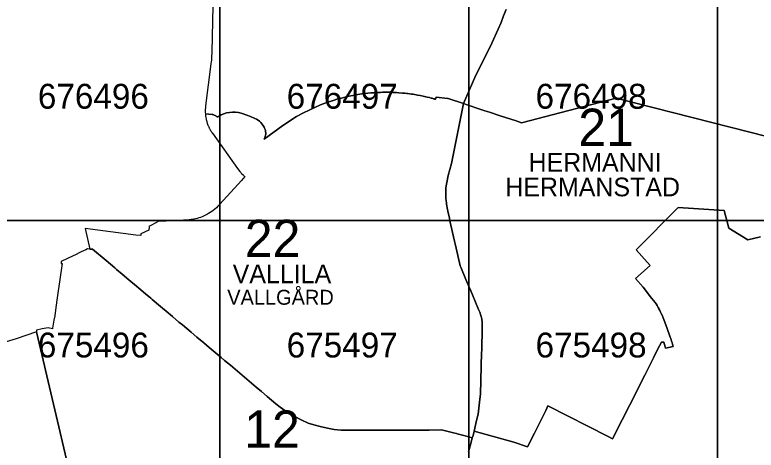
# Model space of a CAD drawing. Extents: x 25485000 to 25520000, y 6656775 to 6690000.
# Drawn here: x 25496176 to 25499155, y 6675077 to 6676827 of the extents above; entities that cross this region are included whole.
import ezdxf

# ---------------------------------------------------------------- set-up
doc = ezdxf.new("R2010")
doc.units = 0
doc.layers.add('Level 63', color=7, linetype='Continuous')

msp = doc.modelspace()

# ---------------------------------------------------------------- linework, layer by layer
at = {"layer": 'Level 63'}
for points in [[(25496000, 6676000), (25497000, 6676000), (25497000, 6677000), (25496000, 6677000)], [(25497000, 6676000), (25498000, 6676000), (25498000, 6677000), (25497000, 6677000)], [(25498000, 6676000), (25499000, 6676000), (25499000, 6677000), (25498000, 6677000)], [(25499000, 6676000), (25500000, 6676000), (25500000, 6677000), (25499000, 6677000)], [(25496458.3, 6675967.8), (25496477.4, 6675885.9), (25496487.8, 6675884.9), (25496542.4, 6675839.5), (25496577.6, 6675809.9), (25496585.2, 6675803.4), (25496606.7, 6675785.4), (25496634.6, 6675761.9), (25496664.8, 6675736.4), (25496674.1, 6675728.6), (25496700.5, 6675706.3), (25496722.3, 6675688), (25496728.4, 6675682.8), (25496736.1, 6675676.4), (25496752.9, 6675662.2), (25496769.7, 6675648.1), (25496783.5, 6675636.4), (25496809.4, 6675614.5), (25496835.4, 6675592.6), (25496849.2, 6675581), (25496866.8, 6675566.2), (25496884.4, 6675551.4), (25496907.4, 6675531.9), (25496934.9, 6675508.7), (25496956.3, 6675490.7), (25497005.3, 6675449.4), (25497019, 6675437.9), (25497042, 6675418.5), (25497145.9, 6675330.8), (25497167.3, 6675312.7), (25497189.6, 6675293.8), (25497207.4, 6675278.7), (25497225.2, 6675263.9), (25497242.3, 6675250.2), (25497271, 6675230), (25497298.1, 6675213.8), (25497326.1, 6675199.3), (25497355.1, 6675186.6), (25497377.1, 6675179), (25497403, 6675172), (25497431.8, 6675165.2), (25497459.8, 6675160.8), (25497487.8, 6675158.1), (25497516.4, 6675157.4), (25497540.6, 6675157.5), (25497558.6, 6675157.6), (25497586, 6675157.7), (25497620.4, 6675157.8), (25497659.4, 6675157.9), (25497700.1, 6675158), (25497725.6, 6675158.2), (25497751.6, 6675158.3), (25497771.6, 6675158.3), (25497840.1, 6675158.4), (25497841.1, 6675158.4), (25497891.1, 6675158.5), (25497938.7, 6675147.2), (25497950.8, 6675144.3), (25497952.9, 6675143.7), (25497985.6, 6675134.5), (25498014.4, 6675126.5), (25498017.2, 6675136.7), (25498021.4, 6675154.1), (25498031.6, 6675196.4), (25498037.8, 6675221.9), (25498045.2, 6675282.7), (25498047.6, 6675303.1), (25498051.9, 6675469.6), (25498052.1, 6675478.1), (25498052.5, 6675492.6), (25498054, 6675555.1), (25498054.6, 6675576.8), (25498054.2, 6675590.9), (25498052.3, 6675605), (25498049, 6675618.7), (25498044.3, 6675632), (25498044, 6675632.8), (25498039.5, 6675643.3), (25498027.5, 6675671.7), (25498015.1, 6675701.2), (25498004.2, 6675727.1), (25498001.8, 6675732.6), (25497988.8, 6675763.4), (25497967.8, 6675813.1), (25497965.7, 6675818.2), (25497956.4, 6675859.3), (25497945.6, 6675907.1), (25497943.4, 6675916.9), (25497924.6, 6675999.8), (25497922.4, 6676009.6), (25497917.1, 6676033), (25497917, 6676033.7), (25497916.5, 6676035.9), (25497916.1, 6676037.8), (25497915.6, 6676039.9), (25497915.4, 6676041.2), (25497914.9, 6676043.5), (25497914.6, 6676045.2), (25497914.2, 6676047), (25497913.9, 6676048.7), (25497913.6, 6676050.7), (25497913.1, 6676053), (25497912.8, 6676054.8), (25497912.6, 6676056.4), (25497911.9, 6676061), (25497911.3, 6676064.8), (25497910.6, 6676069.7), (25497910, 6676074.9), (25497909.7, 6676076.7), (25497909.4, 6676079.1), (25497909, 6676082.2), (25497908.4, 6676087.7), (25497908.3, 6676089.9), (25497908.1, 6676091.5), (25497908, 6676092.7), (25497907.9, 6676094.3), (25497907.9, 6676095.6), (25497907.7, 6676098.2), (25497907.6, 6676102.3), (25497907.5, 6676103.1), (25497907.5, 6676103.5), (25497907.5, 6676106.3), (25497907.5, 6676107.8), (25497907.5, 6676108.7), (25497907.5, 6676110.8), (25497907.5, 6676113.4), (25497907.6, 6676116.4), (25497907.6, 6676118), (25497907.7, 6676119.7), (25497907.8, 6676121.3), (25497908.1, 6676126.4), (25497908.2, 6676127.3), (25497908.2, 6676127.6), (25497908.3, 6676128.5), (25497908.4, 6676129.2), (25497908.5, 6676130.5), (25497909.6, 6676140.6), (25497911.6, 6676153.5), (25497917, 6676181.8), (25497930.1, 6676229.9), (25497978.7, 6676470.5), (25497917, 6676490.8), (25497916.1, 6676490.9), (25497869.1, 6676496.1), (25497866.1, 6676488.1), (25497863.3, 6676488.9), (25497863, 6676489), (25497862.7, 6676489.1), (25497859, 6676490.1), (25497855.4, 6676491.1), (25497852.7, 6676491.9), (25497851.3, 6676492.2), (25497849.5, 6676492.7), (25497841.7, 6676494.7), (25497833.2, 6676496.8), (25497816.8, 6676500.4), (25497805.2, 6676502.8), (25497793.5, 6676505), (25497776.1, 6676507.9), (25497770.4, 6676508.7), (25497763, 6676509.8), (25497755.4, 6676510.7), (25497751.7, 6676511.2), (25497742.8, 6676512.2), (25497737.8, 6676512.7), (25497734.1, 6676513), (25497719.6, 6676514.2), (25497710.2, 6676514.8), (25497694.9, 6676515.6), (25497684.4, 6676515.9), (25497673.4, 6676516), (25497662, 6676516), (25497653.4, 6676515.9), (25497645.1, 6676515.7), (25497631.9, 6676515.1), (25497619.8, 6676514.4), (25497606.8, 6676513.4), (25497594.6, 6676512.2), (25497582.3, 6676510.8), (25497570.8, 6676509.3), (25497555, 6676506.9), (25497543.3, 6676505), (25497534, 6676503.2), (25497526.2, 6676501.7), (25497512.5, 6676498.7), (25497497.6, 6676495.2), (25497488.8, 6676493), (25497480.7, 6676490.8), (25497469.6, 6676487.7), (25497459.8, 6676484.7), (25497446.6, 6676480.6), (25497443.2, 6676479.4), (25497442.4, 6676479.2), (25497436.8, 6676477.3), (25497431.5, 6676475.4), (25497426.3, 6676473.6), (25497414.8, 6676469.3), (25497404.5, 6676465.2), (25497336.4, 6676433.8), (25497310.9, 6676419.4), (25497308.1, 6676418), (25497253.5, 6676382.5), (25497178.5, 6676327.5), (25497181.6, 6676336.4), (25497182.2, 6676338.4), (25497183.4, 6676343.1), (25497184, 6676347.9), (25497184.2, 6676352.7), (25497183.8, 6676357.5), (25497182.9, 6676362.2), (25497181.6, 6676366.8), (25497179.8, 6676371.3), (25497177.5, 6676375.5), (25497172.7, 6676383.3), (25497169.2, 6676388.6), (25497164.5, 6676394.3), (25497159.3, 6676399.4), (25497153.6, 6676404), (25497147.4, 6676407.9), (25497140.8, 6676411.2), (25497122.5, 6676419.1), (25497092.9, 6676429.7), (25497085.7, 6676432), (25497074.2, 6676434.7), (25497062.5, 6676436.1), (25497050.6, 6676436.3), (25497038.8, 6676435.2), (25497027.2, 6676432.9), (25497015.9, 6676429.4), (25497005.1, 6676424.8), (25496994.7, 6676419), (25496994, 6676418.6), (25496993.3, 6676418.3), (25496992.5, 6676418), (25496991.6, 6676417.9), (25496990.8, 6676417.8), (25496990, 6676417.8), (25496989.1, 6676417.9), (25496988.3, 6676418.1), (25496987.5, 6676418.4), (25496986.8, 6676418.7), (25496986, 6676419.1), (25496985.4, 6676419.6), (25496983.1, 6676421.3), (25496980.4, 6676423), (25496977.6, 6676424.3), (25496974.6, 6676425.4), (25496971.6, 6676426.1), (25496968.4, 6676426.5), (25496941.6, 6676429.3), (25496941.7, 6676427.7), (25496941.7, 6676427.3), (25496941.8, 6676426.3), (25496941.9, 6676425.3), (25496942, 6676424.3), (25496942.2, 6676423), (25496942.5, 6676420.1), (25496942.9, 6676417.1), (25496943.4, 6676414.3), (25496944.4, 6676408.9), (25496944.9, 6676407), (25496945, 6676406.3), (25496945.9, 6676402.6), (25496946.9, 6676399), (25496947.7, 6676396), (25496948.6, 6676393.4), (25496949.2, 6676391.4), (25496950.7, 6676387.4), (25496951.9, 6676384.2), (25496952.9, 6676381.7), (25496954, 6676379.3), (25496955.5, 6676375.8), (25496956.5, 6676373.9), (25496957.5, 6676371.9), (25496958.5, 6676369.9), (25496959.8, 6676367.4), (25496959.9, 6676367.3), (25496960.8, 6676365.7), (25496961.4, 6676364.7), (25496961.7, 6676364.1), (25496961.9, 6676363.7), (25496962.4, 6676363), (25496962.6, 6676362.6), (25496963.7, 6676360.8), (25496964.8, 6676359), (25496965.9, 6676357.4), (25496966.5, 6676356.4), (25496967, 6676355.8), (25496968.1, 6676354.2), (25496968.6, 6676353.3), (25496968.8, 6676353.2), (25496969.1, 6676352.7), (25496969.3, 6676352.4), (25496969.4, 6676352.3), (25496970, 6676351.4), (25497071.4, 6676210.1), (25497080.5, 6676197.3), (25497083.6, 6676193.6), (25497085.7, 6676191.2), (25497088.3, 6676188.4), (25497092.9, 6676183.6), (25497095.6, 6676181.1), (25497097.9, 6676179), (25497100.3, 6676176.9), (25497086.7, 6676161.9), (25497044.1, 6676114.7), (25496999, 6676064.8), (25496992.4, 6676057.8), (25496986.1, 6676051.8), (25496980.3, 6676046.7), (25496973.6, 6676041.4), (25496967.9, 6676037.2), (25496960.7, 6676032.3), (25496954.9, 6676028.7), (25496950, 6676025.9), (25496944.7, 6676023), (25496938.9, 6676020.2), (25496933.5, 6676017.8), (25496928.2, 6676015.5), (25496922.3, 6676013.3), (25496914.9, 6676010.8), (25496909, 6676009), (25496902.4, 6676007.4), (25496895.6, 6676005.9), (25496891, 6676005), (25496884.7, 6676004.1), (25496876, 6676003), (25496784.4, 6675998.6), (25496754.5, 6675997.7), (25496725.5, 6675982.2), (25496715, 6675976.5), (25496715.7, 6675973.6), (25496714.6, 6675962.1), (25496682.4, 6675946.9), (25496681.7, 6675939.9), (25496662.9, 6675942.3)], [(25496000, 6675000), (25497000, 6675000), (25497000, 6676000), (25496000, 6676000)], [(25497000, 6675000), (25498000, 6675000), (25498000, 6676000), (25497000, 6676000)], [(25498000, 6675000), (25499000, 6675000), (25499000, 6676000), (25498000, 6676000)], [(25499000, 6675000), (25500000, 6675000), (25500000, 6676000), (25499000, 6676000)]]:
    msp.add_lwpolyline(points, close=True, dxfattribs=at)
for points in [[(25496973.3, 6676926.7), (25496967.4, 6676676.9), (25496967.3, 6676672.8), (25496966.9, 6676661.2), (25496966.5, 6676655.4), (25496966.1, 6676650.3), (25496965.7, 6676645.1), (25496964.9, 6676638), (25496964.1, 6676631), (25496942.8, 6676461.3), (25496942.5, 6676459.5), (25496942.3, 6676457.5), (25496942.2, 6676457.1), (25496942.2, 6676456.7), (25496942.1, 6676456.2), (25496942, 6676454.9), (25496941.9, 6676453.9), (25496941.8, 6676452.8), (25496941.8, 6676452.5), (25496941.7, 6676452.3), (25496941.6, 6676451.2), (25496941.6, 6676450.8), (25496941.4, 6676448.4), (25496941.4, 6676447), (25496941.3, 6676445.6), (25496941.3, 6676444.3), (25496941.2, 6676442.3), (25496941.2, 6676441), (25496941.2, 6676438.5), (25496941.2, 6676437.9), (25496941.2, 6676437.4), (25496941.2, 6676437), (25496941.2, 6676436.8), (25496941.3, 6676436.3), (25496941.3, 6676435.9), (25496941.3, 6676434.7), (25496941.6, 6676429.3), (25496941.7, 6676427.7), (25496941.7, 6676427.3), (25496941.8, 6676426.3), (25496941.9, 6676425.3), (25496942, 6676424.3), (25496942.2, 6676423), (25496942.5, 6676420.1), (25496942.9, 6676417.1), (25496943.4, 6676414.3), (25496944.4, 6676408.9), (25496944.9, 6676407), (25496945, 6676406.3), (25496945.9, 6676402.6), (25496946.9, 6676399), (25496947.7, 6676396), (25496948.6, 6676393.4), (25496949.2, 6676391.4), (25496950.7, 6676387.4), (25496951.9, 6676384.2), (25496952.9, 6676381.7), (25496954, 6676379.3), (25496955.5, 6676375.8), (25496956.5, 6676373.9), (25496957.5, 6676371.9), (25496958.5, 6676369.9), (25496959.8, 6676367.4), (25496959.9, 6676367.3), (25496960.8, 6676365.7), (25496961.4, 6676364.7), (25496961.7, 6676364.1), (25496961.9, 6676363.7), (25496962.4, 6676363), (25496962.6, 6676362.6), (25496963.7, 6676360.8), (25496964.8, 6676359), (25496965.9, 6676357.4), (25496966.5, 6676356.4), (25496967, 6676355.8), (25496968.1, 6676354.2), (25496968.6, 6676353.3), (25496968.8, 6676353.2), (25496969.1, 6676352.7), (25496969.3, 6676352.4), (25496969.4, 6676352.3), (25496970, 6676351.4), (25497071.4, 6676210.1), (25497080.5, 6676197.3), (25497083.6, 6676193.6), (25497085.7, 6676191.2), (25497088.3, 6676188.4), (25497092.9, 6676183.6), (25497095.6, 6676181.1), (25497097.9, 6676179), (25497100.3, 6676176.9), (25497086.7, 6676161.9), (25497044.1, 6676114.7), (25496999, 6676064.8), (25496992.4, 6676057.8), (25496986.1, 6676051.8), (25496980.3, 6676046.7), (25496973.6, 6676041.4), (25496967.9, 6676037.2), (25496960.7, 6676032.3), (25496954.9, 6676028.7), (25496950, 6676025.9), (25496944.7, 6676023), (25496938.9, 6676020.2), (25496933.5, 6676017.8), (25496928.2, 6676015.5), (25496922.3, 6676013.3), (25496914.9, 6676010.8), (25496909, 6676009), (25496902.4, 6676007.4), (25496895.6, 6676005.9), (25496891, 6676005), (25496884.7, 6676004.1), (25496876, 6676003), (25496784.4, 6675998.6), (25496754.5, 6675997.7), (25496725.5, 6675982.2), (25496715, 6675976.5), (25496715.7, 6675973.6), (25496714.6, 6675962.1), (25496682.4, 6675946.9), (25496681.7, 6675939.9), (25496662.9, 6675942.3), (25496458.3, 6675967.8), (25496477.4, 6675885.9), (25496467.6, 6675886.9), (25496460.7, 6675883), (25496442.6, 6675874.1), (25496437.2, 6675871.4), (25496419.5, 6675862.9), (25496410.7, 6675858.5), (25496362.7, 6675835.2), (25496361.9, 6675828), (25496366.4, 6675827.5), (25496345.8, 6675689.9), (25496341.2, 6675650.5), (25496337.4, 6675617.7), (25496332.4, 6675599.9), (25496327.6, 6675567.6), (25496327, 6675564.5), (25496310.6, 6675568.6), (25496286, 6675564.7), (25496262.6, 6675559.9), (25496263.6, 6675552.9), (25496181, 6675525.5), (25496141, 6675513.5)], [(25496973.3, 6676926.7), (25496967.4, 6676676.9), (25496967.3, 6676672.8), (25496966.9, 6676661.2), (25496966.5, 6676655.4), (25496966.1, 6676650.3), (25496965.7, 6676645.1), (25496964.9, 6676638), (25496964.1, 6676631), (25496942.8, 6676461.3), (25496942.5, 6676459.5), (25496942.3, 6676457.5), (25496942.2, 6676457.1), (25496942.2, 6676456.7), (25496942.1, 6676456.2), (25496942, 6676454.9), (25496941.9, 6676453.9), (25496941.8, 6676452.8), (25496941.8, 6676452.5), (25496941.7, 6676452.3), (25496941.6, 6676451.2), (25496941.6, 6676450.8), (25496941.4, 6676448.4), (25496941.4, 6676447), (25496941.3, 6676445.6), (25496941.3, 6676444.3), (25496941.2, 6676442.3), (25496941.2, 6676441), (25496941.2, 6676438.5), (25496941.2, 6676437.9), (25496941.2, 6676437.4), (25496941.2, 6676437), (25496941.2, 6676436.8), (25496941.3, 6676436.3), (25496941.3, 6676435.9), (25496941.3, 6676434.7), (25496941.6, 6676429.3), (25496968.4, 6676426.5), (25496971.6, 6676426.1), (25496974.6, 6676425.4), (25496977.6, 6676424.3), (25496980.4, 6676423), (25496983.1, 6676421.3), (25496985.4, 6676419.6), (25496986, 6676419.1), (25496986.8, 6676418.7), (25496987.5, 6676418.4), (25496988.3, 6676418.1), (25496989.1, 6676417.9), (25496990, 6676417.8), (25496990.8, 6676417.8), (25496991.6, 6676417.9), (25496992.5, 6676418), (25496993.3, 6676418.3), (25496994, 6676418.6), (25496994.7, 6676419), (25497005.1, 6676424.8), (25497015.9, 6676429.4), (25497027.2, 6676432.9), (25497038.8, 6676435.2), (25497050.6, 6676436.3), (25497062.5, 6676436.1), (25497074.2, 6676434.7), (25497085.7, 6676432), (25497092.9, 6676429.7), (25497122.5, 6676419.1), (25497140.8, 6676411.2), (25497147.4, 6676407.9), (25497153.6, 6676404), (25497159.3, 6676399.4), (25497164.5, 6676394.3), (25497169.2, 6676388.6), (25497172.7, 6676383.3), (25497177.5, 6676375.5), (25497179.8, 6676371.3), (25497181.6, 6676366.8), (25497182.9, 6676362.2), (25497183.8, 6676357.5), (25497184.2, 6676352.7), (25497184, 6676347.9), (25497183.4, 6676343.1), (25497182.2, 6676338.4), (25497181.6, 6676336.4), (25497178.5, 6676327.5), (25497253.5, 6676382.5), (25497308.1, 6676418), (25497310.9, 6676419.4), (25497336.4, 6676433.8), (25497404.5, 6676465.2), (25497414.8, 6676469.3), (25497426.3, 6676473.6), (25497431.5, 6676475.4), (25497436.8, 6676477.3), (25497442.4, 6676479.2), (25497443.2, 6676479.4), (25497446.6, 6676480.6), (25497459.8, 6676484.7), (25497469.6, 6676487.7), (25497480.7, 6676490.8), (25497488.8, 6676493), (25497497.6, 6676495.2), (25497512.5, 6676498.7), (25497526.2, 6676501.7), (25497534, 6676503.2), (25497543.3, 6676505), (25497555, 6676506.9), (25497570.8, 6676509.3), (25497582.3, 6676510.8), (25497594.6, 6676512.2), (25497606.8, 6676513.4), (25497619.8, 6676514.4), (25497631.9, 6676515.1), (25497645.1, 6676515.7), (25497653.4, 6676515.9), (25497662, 6676516), (25497673.4, 6676516), (25497684.4, 6676515.9), (25497694.9, 6676515.6), (25497710.2, 6676514.8), (25497719.6, 6676514.2), (25497734.1, 6676513), (25497737.8, 6676512.7), (25497742.8, 6676512.2), (25497751.7, 6676511.2), (25497755.4, 6676510.7), (25497763, 6676509.8), (25497770.4, 6676508.7), (25497776.1, 6676507.9), (25497793.5, 6676505), (25497805.2, 6676502.8), (25497816.8, 6676500.4), (25497833.2, 6676496.8), (25497841.7, 6676494.7), (25497849.5, 6676492.7), (25497851.3, 6676492.2), (25497852.7, 6676491.9), (25497855.4, 6676491.1), (25497859, 6676490.1), (25497862.7, 6676489.1), (25497863, 6676489), (25497863.3, 6676488.9), (25497866.1, 6676488.1), (25497869.1, 6676496.1), (25497916.1, 6676490.9), (25497917, 6676490.8), (25497978.7, 6676470.5), (25498001.4, 6676523.1), (25498027.9, 6676584.3), (25498049, 6676623.9), (25498092.4, 6676713.1), (25498118.2, 6676769.2), (25498129.7, 6676796.5), (25498140.1, 6676822.7), (25498149.9, 6676849)], [(25498149.9, 6676849), (25498140.1, 6676822.7), (25498129.7, 6676796.5), (25498118.2, 6676769.2), (25498092.4, 6676713.1), (25498049, 6676623.9), (25498027.9, 6676584.3), (25498001.4, 6676523.1), (25497978.7, 6676470.5), (25497994, 6676465.4), (25498048.6, 6676447.4), (25498064.8, 6676442.1), (25498082.9, 6676436.1), (25498126.2, 6676421.9), (25498190.7, 6676400.6), (25498212.6, 6676393.4), (25498592.6, 6676492.8), (25499887.6, 6676162.5)], [(25499887.6, 6676162.5), (25498592.6, 6676492.8), (25498212.6, 6676393.4), (25498190.7, 6676400.6), (25498126.2, 6676421.9), (25498082.9, 6676436.1), (25498064.8, 6676442.1), (25498048.6, 6676447.4), (25497994, 6676465.4), (25497978.7, 6676470.5), (25497930.1, 6676229.9), (25497917, 6676181.8), (25497911.6, 6676153.5), (25497909.6, 6676140.6), (25497908.5, 6676130.5), (25497908.4, 6676129.2), (25497908.3, 6676128.5), (25497908.2, 6676127.6), (25497908.2, 6676127.3), (25497908.1, 6676126.4), (25497907.8, 6676121.3), (25497907.7, 6676119.7), (25497907.6, 6676118), (25497907.6, 6676116.4), (25497907.5, 6676113.4), (25497907.5, 6676110.8), (25497907.5, 6676108.7), (25497907.5, 6676107.8), (25497907.5, 6676106.3), (25497907.5, 6676103.5), (25497907.5, 6676103.1), (25497907.6, 6676102.3), (25497907.7, 6676098.2), (25497907.9, 6676095.6), (25497907.9, 6676094.3), (25497908, 6676092.7), (25497908.1, 6676091.5), (25497908.3, 6676089.9), (25497908.4, 6676087.7), (25497909, 6676082.2), (25497909.4, 6676079.1), (25497909.7, 6676076.7), (25497910, 6676074.9), (25497910.6, 6676069.7), (25497911.3, 6676064.8), (25497911.9, 6676061), (25497912.6, 6676056.4), (25497912.8, 6676054.8), (25497913.1, 6676053), (25497913.6, 6676050.7), (25497913.9, 6676048.7), (25497914.2, 6676047), (25497914.6, 6676045.2), (25497914.9, 6676043.5), (25497915.4, 6676041.2), (25497915.6, 6676039.9), (25497916.1, 6676037.8), (25497916.5, 6676035.9), (25497917, 6676033.7), (25497917.1, 6676033), (25497922.4, 6676009.6), (25497924.6, 6675999.8), (25497943.4, 6675916.9), (25497945.6, 6675907.1), (25497956.4, 6675859.3), (25497965.7, 6675818.2), (25497967.8, 6675813.1), (25497988.8, 6675763.4), (25498001.8, 6675732.6), (25498004.2, 6675727.1), (25498015.1, 6675701.2), (25498027.5, 6675671.7), (25498039.5, 6675643.3), (25498044, 6675632.8), (25498044.3, 6675632), (25498049, 6675618.7), (25498052.3, 6675605), (25498054.2, 6675590.9), (25498054.6, 6675576.8), (25498054, 6675555.1), (25498052.5, 6675492.6), (25498052.1, 6675478.1), (25498051.9, 6675469.6), (25498047.6, 6675303.1), (25498045.2, 6675282.7), (25498037.8, 6675221.9), (25498031.6, 6675196.4), (25498021.4, 6675154.1), (25498181.1, 6675109), (25498235.5, 6675090.7), (25498263.6, 6675146), (25498309.4, 6675236.8), (25498317.5, 6675255.2), (25498560.3, 6675132.5), (25498578.2, 6675123.5), (25498588.1, 6675143.1), (25498598.3, 6675163.3), (25498616.3, 6675199), (25498676.3, 6675317.9), (25498684.5, 6675334.1), (25498707, 6675378.8), (25498742.4, 6675448.9), (25498758.8, 6675481.4), (25498774.1, 6675511.8), (25498783.5, 6675511.8), (25498789.5, 6675492.4), (25498790.8, 6675487.6), (25498821.9, 6675493.5), (25498820.1, 6675499.7), (25498818.9, 6675504), (25498817.5, 6675508.7), (25498817, 6675510.2), (25498815.2, 6675516.1), (25498813.7, 6675520.8), (25498811.7, 6675526.9), (25498810, 6675531.6), (25498808.5, 6675535.9), (25498797.5, 6675566.5), (25498779.6, 6675613.6), (25498778.4, 6675616.3), (25498775.6, 6675622.5), (25498774.6, 6675624.7), (25498774.1, 6675625.7), (25498773.6, 6675626.8), (25498770.8, 6675632.6), (25498767.5, 6675639.2), (25498764.3, 6675645.5), (25498763.4, 6675647.2), (25498761.1, 6675651.4), (25498758.3, 6675656.5), (25498756.9, 6675658.8), (25498753.2, 6675665.2), (25498749.6, 6675671.2), (25498729.7, 6675695.5), (25498722.5, 6675705.1), (25498700.4, 6675732.6), (25498669.6, 6675768), (25498728.6, 6675819.3), (25498673.2, 6675883), (25498842.2, 6676052.9), (25499027, 6676040.2), (25499044.8, 6675969.9), (25499122.2, 6675923.5), (25499172.3, 6675934.6)], [(25499172.3, 6675934.6), (25499122.2, 6675923.5), (25499044.8, 6675969.9), (25499027, 6676040.2), (25498842.2, 6676052.9), (25498673.2, 6675883), (25498728.6, 6675819.3), (25498669.6, 6675768), (25498700.4, 6675732.6), (25498722.5, 6675705.1), (25498729.7, 6675695.5), (25498749.6, 6675671.2), (25498753.2, 6675665.2), (25498756.9, 6675658.8), (25498758.3, 6675656.5), (25498761.1, 6675651.4), (25498763.4, 6675647.2), (25498764.3, 6675645.5), (25498767.5, 6675639.2), (25498770.8, 6675632.6), (25498773.6, 6675626.8), (25498774.1, 6675625.7), (25498774.6, 6675624.7), (25498775.6, 6675622.5), (25498778.4, 6675616.3), (25498779.6, 6675613.6), (25498797.5, 6675566.5), (25498808.5, 6675535.9), (25498810, 6675531.6), (25498811.7, 6675526.9), (25498813.7, 6675520.8), (25498815.2, 6675516.1), (25498817, 6675510.2), (25498817.5, 6675508.7), (25498818.9, 6675504), (25498820.1, 6675499.7), (25498821.9, 6675493.5), (25498790.8, 6675487.6), (25498789.5, 6675492.4), (25498783.5, 6675511.8), (25498774.1, 6675511.8), (25498758.8, 6675481.4), (25498742.4, 6675448.9), (25498707, 6675378.8), (25498684.5, 6675334.1), (25498676.3, 6675317.9), (25498616.3, 6675199), (25498598.3, 6675163.3), (25498588.1, 6675143.1), (25498578.2, 6675123.5), (25498560.3, 6675132.5), (25498317.5, 6675255.2), (25498309.4, 6675236.8), (25498263.6, 6675146), (25498235.5, 6675090.7), (25498181.1, 6675109), (25498021.4, 6675154.1), (25498017.2, 6675136.7), (25498014.4, 6675126.5), (25498008.1, 6675103.9), (25497999.1, 6675071.1)], [(25497999.1, 6675071.1), (25498008.1, 6675103.9), (25498014.4, 6675126.5), (25497985.6, 6675134.5), (25497952.9, 6675143.7), (25497950.8, 6675144.3), (25497938.7, 6675147.2), (25497891.1, 6675158.5), (25497841.1, 6675158.4), (25497840.1, 6675158.4), (25497771.6, 6675158.3), (25497751.6, 6675158.3), (25497725.6, 6675158.2), (25497700.1, 6675158), (25497659.4, 6675157.9), (25497620.4, 6675157.8), (25497586, 6675157.7), (25497558.6, 6675157.6), (25497540.6, 6675157.5), (25497516.4, 6675157.4), (25497487.8, 6675158.1), (25497459.8, 6675160.8), (25497431.8, 6675165.2), (25497403, 6675172), (25497377.1, 6675179), (25497355.1, 6675186.6), (25497326.1, 6675199.3), (25497298.1, 6675213.8), (25497271, 6675230), (25497242.3, 6675250.2), (25497225.2, 6675263.9), (25497207.4, 6675278.7), (25497189.6, 6675293.8), (25497167.3, 6675312.7), (25497145.9, 6675330.8), (25497042, 6675418.5), (25497019, 6675437.9), (25497005.3, 6675449.4), (25496956.3, 6675490.7), (25496934.9, 6675508.7), (25496907.4, 6675531.9), (25496884.4, 6675551.4), (25496866.8, 6675566.2), (25496849.2, 6675581), (25496835.4, 6675592.6), (25496809.4, 6675614.5), (25496783.5, 6675636.4), (25496769.7, 6675648.1), (25496752.9, 6675662.2), (25496736.1, 6675676.4), (25496728.4, 6675682.8), (25496722.3, 6675688), (25496700.5, 6675706.3), (25496674.1, 6675728.6), (25496664.8, 6675736.4), (25496634.6, 6675761.9), (25496606.7, 6675785.4), (25496585.2, 6675803.4), (25496577.6, 6675809.9), (25496542.4, 6675839.5), (25496487.8, 6675884.9), (25496477.4, 6675885.9), (25496467.6, 6675886.9), (25496460.7, 6675883), (25496442.6, 6675874.1), (25496437.2, 6675871.4), (25496419.5, 6675862.9), (25496410.7, 6675858.5), (25496362.7, 6675835.2), (25496361.9, 6675828), (25496366.4, 6675827.5), (25496345.8, 6675689.9), (25496341.2, 6675650.5), (25496337.4, 6675617.7), (25496332.4, 6675599.9), (25496327.6, 6675567.6), (25496327, 6675564.5), (25496310.6, 6675568.6), (25496286, 6675564.7), (25496262.6, 6675559.9), (25496263.6, 6675552.9), (25496462.5, 6674704.2)], [(25496462.5, 6674704.2), (25496263.6, 6675552.9), (25496181, 6675525.5), (25496141, 6675513.5)]]:
    msp.add_lwpolyline(points, dxfattribs=at)

# ---------------------------------------------------------------- texts
for s, height, p in [('676496', 100, (25496268.5, 6676450)), ('676497', 100, (25497268.5, 6676450)), ('676498', 100, (25498268.5, 6676450)), ('21', 150, (25498440.5, 6676300.2)), ('HERMANNI', 75, (25498240.2, 6676197.2)), ('HERMANSTAD', 75, (25498146.8, 6676097.9)), ('22', 150, (25497100.3, 6675853.8)), ('VALLILA', 75, (25497051.5, 6675748.7)), ('VALLGÅRD', 60, (25497029.6, 6675662)), ('675496', 100, (25496268.5, 6675450)), ('675497', 100, (25497268.5, 6675450)), ('675498', 100, (25498268.5, 6675450)), ('12', 150, (25497097.9, 6675086.9))]:
    msp.add_text(s, height=height, dxfattribs=at).set_placement(p)

doc.saveas('drawing.dxf')
